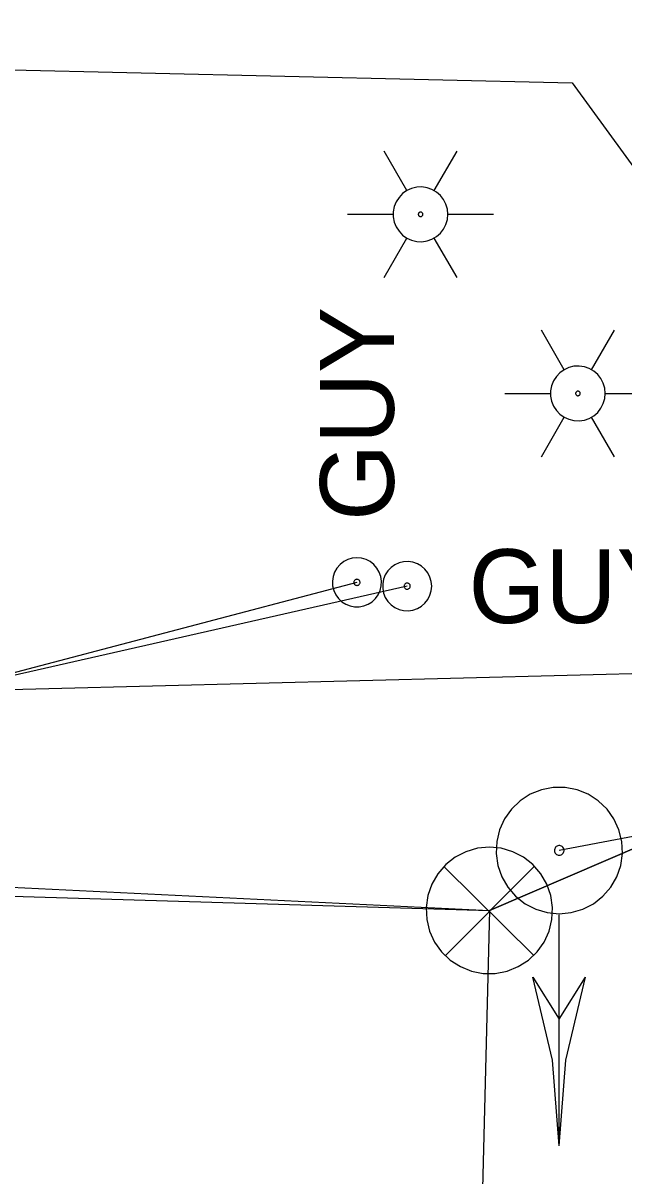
# Model space of a CAD drawing. Extents: x 596028 to 606371, y 330010 to 403088.
# Drawn here: x 604644.7 to 604676.1, y 339404.4 to 339464.5 of the extents above; entities that cross this region are included whole.
import ezdxf

# ---------------------------------------------------------------- set-up
doc = ezdxf.new("R2010")
doc.units = 0
for name, color, linetype in [('E_LTG', 7, 'Continuous'), ('E_SIG', 7, 'Continuous'), ('E_SIG_Conduit', 7, 'Continuous'), ('E_UTL_EGuyWire', 7, 'Continuous'), ('E_UTL_FO_UG', 7, 'Continuous'), ('E_UTL_Loop_UG', 7, 'Continuous'), ('E_UTL_Overhead', 7, 'Continuous'), ('E_UTL_W_UG', 7, 'Continuous')]:
    doc.layers.add(name, color=color, linetype=linetype)

msp = doc.modelspace()

# ---------------------------------------------------------------- linework, layer by layer
at = {"layer": 'E_LTG'}
for points in [[(604664.786, 339455.777), (604663.595, 339457.839)], [(604666.214, 339455.777), (604667.405, 339457.839)], [(604666.929, 339454.539), (604666.903, 339454.809), (604666.827, 339455.07), (604666.702, 339455.312), (604666.534, 339455.525), (604666.329, 339455.703), (604666.094, 339455.839), (604665.837, 339455.928), (604665.568, 339455.966), (604665.297, 339455.953), (604665.033, 339455.889), (604664.786, 339455.777), (604664.564, 339455.619), (604664.377, 339455.422), (604664.23, 339455.194), (604664.129, 339454.942), (604664.077, 339454.675), (604664.077, 339454.403), (604664.129, 339454.136), (604664.23, 339453.884), (604664.377, 339453.656), (604664.564, 339453.459), (604664.786, 339453.301), (604665.033, 339453.189), (604665.297, 339453.125), (604665.568, 339453.112), (604665.837, 339453.15), (604666.094, 339453.239), (604666.329, 339453.375), (604666.534, 339453.553), (604666.702, 339453.766), (604666.827, 339454.008), (604666.903, 339454.269), (604666.929, 339454.539)], [(604666.929, 339454.539), (604666.903, 339454.809), (604666.827, 339455.07), (604666.702, 339455.312), (604666.534, 339455.525), (604666.329, 339455.703), (604666.094, 339455.839), (604665.837, 339455.928), (604665.568, 339455.966), (604665.297, 339455.953), (604665.033, 339455.889), (604664.786, 339455.777), (604664.564, 339455.619), (604664.377, 339455.422), (604664.23, 339455.194), (604664.129, 339454.942), (604664.077, 339454.675), (604664.077, 339454.403), (604664.129, 339454.136), (604664.23, 339453.884), (604664.377, 339453.656), (604664.564, 339453.459), (604664.786, 339453.301), (604665.033, 339453.189), (604665.297, 339453.125), (604665.568, 339453.112), (604665.837, 339453.15), (604666.094, 339453.239), (604666.329, 339453.375), (604666.534, 339453.553), (604666.702, 339453.766), (604666.827, 339454.008), (604666.903, 339454.269), (604666.929, 339454.539)], [(604666.929, 339454.539), (604666.903, 339454.809), (604666.827, 339455.07), (604666.702, 339455.312), (604666.534, 339455.525), (604666.329, 339455.703), (604666.094, 339455.839), (604665.837, 339455.928), (604665.568, 339455.966), (604665.297, 339455.953), (604665.033, 339455.889), (604664.786, 339455.777), (604664.564, 339455.619), (604664.377, 339455.422), (604664.23, 339455.194), (604664.129, 339454.942), (604664.077, 339454.675), (604664.077, 339454.403), (604664.129, 339454.136), (604664.23, 339453.884), (604664.377, 339453.656), (604664.564, 339453.459), (604664.786, 339453.301), (604665.033, 339453.189), (604665.297, 339453.125), (604665.568, 339453.112), (604665.837, 339453.15), (604666.094, 339453.239), (604666.329, 339453.375), (604666.534, 339453.553), (604666.702, 339453.766), (604666.827, 339454.008), (604666.903, 339454.269), (604666.929, 339454.539)], [(604661.689, 339454.539), (604664.071, 339454.539)], [(604665.619, 339454.539), (604665.617, 339454.562), (604665.611, 339454.583), (604665.6, 339454.603), (604665.586, 339454.621), (604665.569, 339454.636), (604665.549, 339454.647), (604665.528, 339454.655), (604665.506, 339454.658), (604665.483, 339454.657), (604665.461, 339454.652), (604665.44, 339454.642), (604665.422, 339454.629), (604665.406, 339454.613), (604665.394, 339454.594), (604665.386, 339454.573), (604665.381, 339454.55), (604665.381, 339454.528), (604665.386, 339454.505), (604665.394, 339454.484), (604665.406, 339454.465), (604665.422, 339454.449), (604665.44, 339454.436), (604665.461, 339454.426), (604665.483, 339454.421), (604665.506, 339454.42), (604665.528, 339454.423), (604665.549, 339454.431), (604665.569, 339454.442), (604665.586, 339454.457), (604665.6, 339454.475), (604665.611, 339454.495), (604665.617, 339454.516), (604665.619, 339454.539)], [(604666.929, 339454.539), (604669.311, 339454.539)], [(604663.595, 339451.239), (604664.786, 339453.302)], [(604667.405, 339451.239), (604666.214, 339453.302)], [(604672.999, 339446.435), (604671.808, 339448.497)], [(604674.427, 339446.435), (604675.618, 339448.497)], [(604675.142, 339445.197), (604675.116, 339445.467), (604675.04, 339445.728), (604674.915, 339445.97), (604674.747, 339446.183), (604674.542, 339446.361), (604674.307, 339446.497), (604674.05, 339446.586), (604673.781, 339446.624), (604673.51, 339446.611), (604673.246, 339446.547), (604672.999, 339446.435), (604672.777, 339446.277), (604672.59, 339446.08), (604672.443, 339445.852), (604672.342, 339445.6), (604672.29, 339445.333), (604672.29, 339445.061), (604672.342, 339444.794), (604672.443, 339444.542), (604672.59, 339444.314), (604672.777, 339444.117), (604672.999, 339443.959), (604673.246, 339443.847), (604673.51, 339443.783), (604673.781, 339443.77), (604674.05, 339443.808), (604674.307, 339443.897), (604674.542, 339444.033), (604674.747, 339444.211), (604674.915, 339444.424), (604675.04, 339444.666), (604675.116, 339444.927), (604675.142, 339445.197)], [(604675.142, 339445.197), (604675.116, 339445.467), (604675.04, 339445.728), (604674.915, 339445.97), (604674.747, 339446.183), (604674.542, 339446.361), (604674.307, 339446.497), (604674.05, 339446.586), (604673.781, 339446.624), (604673.51, 339446.611), (604673.246, 339446.547), (604672.999, 339446.435), (604672.777, 339446.277), (604672.59, 339446.08), (604672.443, 339445.852), (604672.342, 339445.6), (604672.29, 339445.333), (604672.29, 339445.061), (604672.342, 339444.794), (604672.443, 339444.542), (604672.59, 339444.314), (604672.777, 339444.117), (604672.999, 339443.959), (604673.246, 339443.847), (604673.51, 339443.783), (604673.781, 339443.77), (604674.05, 339443.808), (604674.307, 339443.897), (604674.542, 339444.033), (604674.747, 339444.211), (604674.915, 339444.424), (604675.04, 339444.666), (604675.116, 339444.927), (604675.142, 339445.197)], [(604675.142, 339445.197), (604675.116, 339445.467), (604675.04, 339445.728), (604674.915, 339445.97), (604674.747, 339446.183), (604674.542, 339446.361), (604674.307, 339446.497), (604674.05, 339446.586), (604673.781, 339446.624), (604673.51, 339446.611), (604673.246, 339446.547), (604672.999, 339446.435), (604672.777, 339446.277), (604672.59, 339446.08), (604672.443, 339445.852), (604672.342, 339445.6), (604672.29, 339445.333), (604672.29, 339445.061), (604672.342, 339444.794), (604672.443, 339444.542), (604672.59, 339444.314), (604672.777, 339444.117), (604672.999, 339443.959), (604673.246, 339443.847), (604673.51, 339443.783), (604673.781, 339443.77), (604674.05, 339443.808), (604674.307, 339443.897), (604674.542, 339444.033), (604674.747, 339444.211), (604674.915, 339444.424), (604675.04, 339444.666), (604675.116, 339444.927), (604675.142, 339445.197)], [(604669.902, 339445.197), (604672.284, 339445.197)], [(604673.832, 339445.197), (604673.83, 339445.22), (604673.824, 339445.241), (604673.813, 339445.261), (604673.799, 339445.279), (604673.782, 339445.294), (604673.762, 339445.305), (604673.741, 339445.313), (604673.719, 339445.316), (604673.696, 339445.315), (604673.674, 339445.31), (604673.653, 339445.3), (604673.635, 339445.287), (604673.619, 339445.271), (604673.607, 339445.252), (604673.599, 339445.231), (604673.594, 339445.208), (604673.594, 339445.186), (604673.599, 339445.163), (604673.607, 339445.142), (604673.619, 339445.123), (604673.635, 339445.107), (604673.653, 339445.094), (604673.674, 339445.084), (604673.696, 339445.079), (604673.719, 339445.078), (604673.741, 339445.081), (604673.762, 339445.089), (604673.782, 339445.1), (604673.799, 339445.115), (604673.813, 339445.133), (604673.824, 339445.153), (604673.83, 339445.174), (604673.832, 339445.197)], [(604675.142, 339445.197), (604677.524, 339445.197)], [(604671.808, 339441.897), (604672.999, 339443.96)], [(604675.618, 339441.897), (604674.427, 339443.96)]]:
    msp.add_lwpolyline(points, dxfattribs=at)
at = {"layer": 'E_SIG'}
for points in [[(604672.74, 339418.06), (604673.365, 339418.12), (604673.967, 339418.297), (604674.524, 339418.584), (604675.017, 339418.972), (604675.428, 339419.446), (604675.742, 339419.989), (604675.947, 339420.582), (604676.036, 339421.203), (604676.007, 339421.83), (604675.859, 339422.44), (604675.598, 339423.01), (604675.234, 339423.521), (604674.78, 339423.954), (604674.252, 339424.294), (604673.67, 339424.527), (604673.054, 339424.645), (604672.426, 339424.645), (604671.81, 339424.527), (604671.228, 339424.294), (604670.7, 339423.954), (604670.246, 339423.521), (604669.882, 339423.01), (604669.622, 339422.44), (604669.474, 339421.83), (604669.444, 339421.203), (604669.533, 339420.582), (604669.738, 339419.989), (604670.052, 339419.446), (604670.463, 339418.972), (604670.956, 339418.584), (604671.514, 339418.297), (604672.116, 339418.12), (604672.74, 339418.06)], [(604669.09, 339421.533), (604668.465, 339421.473), (604667.863, 339421.296), (604667.305, 339421.009), (604666.812, 339420.621), (604666.401, 339420.147), (604666.088, 339419.604), (604665.883, 339419.011), (604665.793, 339418.39), (604665.823, 339417.763), (604665.971, 339417.154), (604666.232, 339416.583), (604666.596, 339416.072), (604667.05, 339415.639), (604667.577, 339415.3), (604668.16, 339415.067), (604668.776, 339414.948), (604669.403, 339414.948), (604670.019, 339415.067), (604670.602, 339415.3), (604671.129, 339415.639), (604671.583, 339416.072), (604671.947, 339416.583), (604672.208, 339417.154), (604672.356, 339417.763), (604672.386, 339418.39), (604672.296, 339419.011), (604672.091, 339419.604), (604671.778, 339420.147), (604671.367, 339420.621), (604670.874, 339421.009), (604670.316, 339421.296), (604669.714, 339421.473), (604669.09, 339421.533)], [(604672.74, 339421.108), (604672.788, 339421.113), (604672.834, 339421.126), (604672.877, 339421.148), (604672.914, 339421.178), (604672.946, 339421.214), (604672.97, 339421.256), (604672.985, 339421.301), (604672.992, 339421.348), (604672.99, 339421.396), (604672.979, 339421.443), (604672.959, 339421.487), (604672.931, 339421.526), (604672.896, 339421.559), (604672.856, 339421.585), (604672.811, 339421.603), (604672.764, 339421.612), (604672.716, 339421.612), (604672.669, 339421.603), (604672.624, 339421.585), (604672.584, 339421.559), (604672.549, 339421.526), (604672.522, 339421.487), (604672.502, 339421.443), (604672.49, 339421.396), (604672.488, 339421.348), (604672.495, 339421.301), (604672.511, 339421.256), (604672.535, 339421.214), (604672.566, 339421.178), (604672.604, 339421.148), (604672.646, 339421.126), (604672.692, 339421.113), (604672.74, 339421.108)], [(604666.755, 339420.495), (604671.412, 339415.885)], [(604666.803, 339415.885), (604671.455, 339420.538)], [(604672.739, 339405.961), (604672.739, 339418.002)], [(604672.74, 339405.96), (604672.394, 339410.414), (604671.365, 339414.76)], [(604671.367, 339414.76), (604672.739, 339412.56)], [(604672.739, 339412.56), (604674.116, 339414.76)], [(604672.74, 339405.96), (604673.086, 339410.414), (604674.115, 339414.76)]]:
    msp.add_lwpolyline(points, dxfattribs=at)
at = {"layer": 'E_SIG_Conduit'}
msp.add_line((604534.037, 339424.821), (604669.091, 339418.231), dxfattribs=at)
for points in [[(604679.261, 339422.591), (604669.091, 339418.231)], [(604679.261, 339422.591), (604672.741, 339421.361)]]:
    msp.add_lwpolyline(points, dxfattribs=at)
at = {"layer": 'E_UTL_EGuyWire'}
for p in [(604662.18, 339435.343), (604664.8, 339435.146)]:
    msp.add_line(p, (604640.658, 339429.671), dxfattribs=at)
for points in [[(604662.18, 339436.626), (604661.937, 339436.603), (604661.703, 339436.534), (604661.486, 339436.423), (604661.294, 339436.272), (604661.135, 339436.087), (604661.013, 339435.876), (604660.933, 339435.646), (604660.898, 339435.404), (604660.91, 339435.16), (604660.967, 339434.923), (604661.069, 339434.701), (604661.21, 339434.503), (604661.387, 339434.334), (604661.592, 339434.202), (604661.818, 339434.112), (604662.058, 339434.065), (604662.302, 339434.065), (604662.542, 339434.112), (604662.768, 339434.202), (604662.973, 339434.334), (604663.15, 339434.503), (604663.291, 339434.701), (604663.393, 339434.923), (604663.45, 339435.16), (604663.462, 339435.404), (604663.427, 339435.646), (604663.347, 339435.876), (604663.225, 339436.087), (604663.066, 339436.272), (604662.874, 339436.423), (604662.657, 339436.534), (604662.423, 339436.603), (604662.18, 339436.626)], [(604666.083, 339435.146), (604666.06, 339435.389), (604665.991, 339435.623), (604665.88, 339435.84), (604665.729, 339436.032), (604665.544, 339436.191), (604665.333, 339436.313), (604665.103, 339436.393), (604664.861, 339436.428), (604664.617, 339436.416), (604664.38, 339436.359), (604664.158, 339436.257), (604663.96, 339436.116), (604663.791, 339435.939), (604663.659, 339435.734), (604663.569, 339435.508), (604663.522, 339435.268), (604663.522, 339435.024), (604663.569, 339434.784), (604663.659, 339434.558), (604663.791, 339434.353), (604663.96, 339434.176), (604664.158, 339434.035), (604664.38, 339433.933), (604664.617, 339433.876), (604664.861, 339433.864), (604665.103, 339433.899), (604665.333, 339433.979), (604665.544, 339434.101), (604665.729, 339434.26), (604665.88, 339434.452), (604665.991, 339434.669), (604666.06, 339434.903), (604666.083, 339435.146)], [(604662.18, 339435.503), (604662.15, 339435.501), (604662.12, 339435.492), (604662.093, 339435.478), (604662.069, 339435.459), (604662.049, 339435.436), (604662.034, 339435.41), (604662.024, 339435.381), (604662.02, 339435.351), (604662.021, 339435.32), (604662.028, 339435.291), (604662.041, 339435.263), (604662.059, 339435.238), (604662.081, 339435.217), (604662.106, 339435.2), (604662.135, 339435.189), (604662.165, 339435.183), (604662.195, 339435.183), (604662.225, 339435.189), (604662.254, 339435.2), (604662.279, 339435.217), (604662.301, 339435.238), (604662.319, 339435.263), (604662.332, 339435.291), (604662.339, 339435.32), (604662.34, 339435.351), (604662.336, 339435.381), (604662.326, 339435.41), (604662.311, 339435.436), (604662.291, 339435.459), (604662.267, 339435.478), (604662.24, 339435.492), (604662.21, 339435.501), (604662.18, 339435.503)], [(604664.96, 339435.146), (604664.958, 339435.176), (604664.949, 339435.206), (604664.935, 339435.233), (604664.916, 339435.257), (604664.893, 339435.277), (604664.867, 339435.292), (604664.838, 339435.302), (604664.808, 339435.306), (604664.777, 339435.305), (604664.748, 339435.298), (604664.72, 339435.285), (604664.695, 339435.267), (604664.674, 339435.245), (604664.657, 339435.22), (604664.646, 339435.191), (604664.64, 339435.161), (604664.64, 339435.131), (604664.646, 339435.101), (604664.657, 339435.072), (604664.674, 339435.047), (604664.695, 339435.025), (604664.72, 339435.007), (604664.748, 339434.994), (604664.777, 339434.987), (604664.808, 339434.986), (604664.838, 339434.99), (604664.867, 339435), (604664.893, 339435.015), (604664.916, 339435.035), (604664.935, 339435.059), (604664.949, 339435.086), (604664.958, 339435.116), (604664.96, 339435.146)]]:
    msp.add_lwpolyline(points, dxfattribs=at)
at = {"layer": 'E_UTL_FO_UG'}
msp.add_lwpolyline([(604540.375, 339422.08), (604669.091, 339418.231), (604679.261, 339422.591)], dxfattribs=at)
at = {"layer": 'E_UTL_Loop_UG'}
msp.add_line((604669.091, 339418.231), (604668.606, 339398.668), dxfattribs=at)
at = {"layer": 'E_UTL_Overhead'}
msp.add_lwpolyline([(604487.168, 339458.603), (604640.658, 339429.671), (604683.979, 339430.78), (604818.922, 339403.26), (604974.133, 339363.63), (605153.062, 339361.475)], dxfattribs=at)
at = {"layer": 'E_UTL_W_UG'}
msp.add_line((604536.91, 339464.515), (604673.415, 339461.4), dxfattribs=at)
msp.add_lwpolyline([(604673.415, 339461.4), (604686.537, 339443.406), (604745.201, 339452.301), (604755.11, 339453.801), (604801.174, 339464.209)], dxfattribs=at)

# ---------------------------------------------------------------- texts
at = {"layer": 'E_UTL_EGuyWire'}
msp.add_text('GUY', height=3.85, rotation=90, dxfattribs=at).set_placement((604664.105, 339438.551))
msp.add_text('GUY', height=3.85, dxfattribs=at).set_placement((604668.008, 339433.221))

doc.saveas('drawing.dxf')
